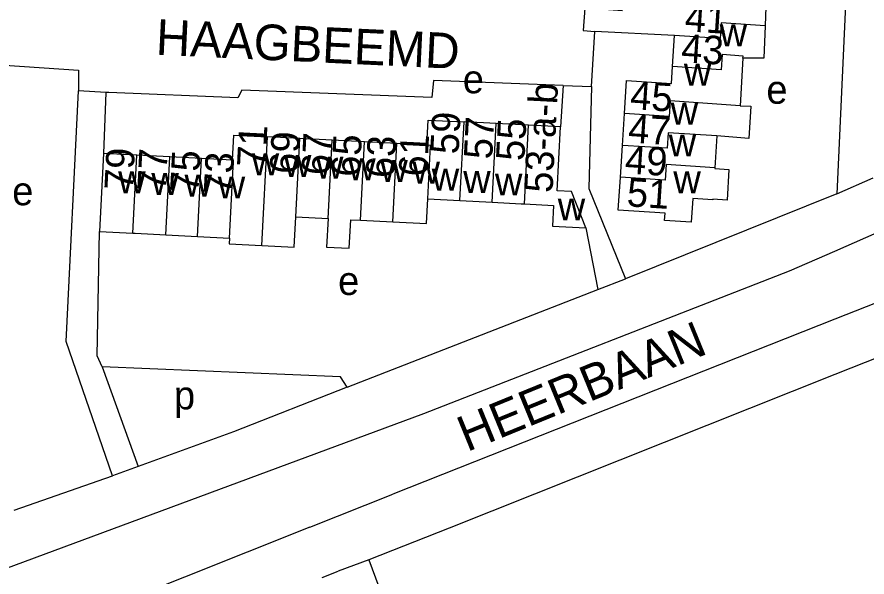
# Model space of a CAD drawing. Extents: x 163026 to 166241, y 382475 to 384501.
# Drawn here: x 164584.9 to 164704.5, y 383524.4 to 383603.1 of the extents above; entities that cross this region are included whole.
import ezdxf

# ---------------------------------------------------------------- set-up
doc = ezdxf.new("R2010")
doc.units = 0
for name, color, linetype in [('BLT_Basislijn', 7, 'Continuous'), ('BLT_Bebouwing', 7, 'Continuous'), ('BLT_Centroide', 7, 'Continuous'), ('BLT_Huisnummer', 7, 'Continuous'), ('BLT_Huisnummer_ tussenligend', 7, 'Continuous'), ('BLT_Huisnummer_reeks', 7, 'Continuous'), ('BLT_Onderverdeling_panden', 7, 'Continuous'), ('BLT_Straatnaam', 7, 'Continuous')]:
    doc.layers.add(name, color=color, linetype=linetype)

msp = doc.modelspace()

# ---------------------------------------------------------------- linework, layer by layer
at = {"layer": 'BLT_Basislijn'}
for p, q in [((164702.47, 383626.32), (164700.28, 383578.28)), ((164597.43, 383592.54), (164593.58, 383592.75)), ((164597.43, 383592.54), (164597.11, 383583.96)), ((164661.76, 383593.51), (164661.4, 383587.68)), ((164661.76, 383593.51), (164665.75, 383593.35)), ((164700.28, 383578.28), (164705.39, 383580.51)), ((164666.65, 383564.81), (164670.52, 383566.32)), ((164631.39, 383551.09), (164666.65, 383564.81)), ((164596.89, 383553.95), (164601.96, 383539.9)), ((164584.51, 383533.77), (164598.35, 383538.59)), ((164626.13, 383531.38), (164637.79, 383536.01)), ((164634.42, 383526.8), (164630.09, 383525.2)), ((164627.88, 383524.32), (164630.09, 383525.2))]:
    msp.add_line(p, q, dxfattribs=at)
for points in [[(164316.74, 383637.52), (164399.59, 383569.15), (164439.68, 383536.44), (164449.09, 383529.98), (164458.65, 383524.65), (164472.19, 383518.92), (164485.74, 383514.54), (164499.92, 383512), (164504.7, 383511.64), (164519.36, 383511.35), (164533, 383512.62), (164547.18, 383515.25), (164581.89, 383525.04), (164642.18, 383547.36), (164693.59, 383567.42), (164700, 383570.19), (164761.7, 383597.42), (164778.75, 383605.71), (164783.1, 383609.13), (164785.13, 383612.46), (164785.97, 383614.66), (164786.37, 383617.55)], [(164665.75, 383593.35), (164666.22, 383601.12)], [(164583.2, 383596.39), (164593.59, 383595.68), (164593.58, 383592.75)], [(164661.76, 383593.51), (164643.54, 383594.21), (164643.27, 383591.84), (164616.57, 383592.86), (164615.99, 383591.79), (164597.85, 383592.51), (164597.43, 383592.54)], [(164598.35, 383538.59), (164591.87, 383557.48), (164593.58, 383592.75)], [(164792.86, 383589.8), (164791.18, 383591.89), (164789.33, 383592.7), (164786.4, 383593.36), (164781.85, 383592.83), (164700, 383560.63), (164637.79, 383536.01)], [(164665.75, 383593.35), (164665.37, 383579.02), (164670.52, 383566.32)], [(164787.8, 383587.61), (164700, 383552.86), (164645.73, 383531.25), (164634.42, 383526.8)], [(164700.28, 383578.28), (164670.52, 383566.32)], [(164664.96, 383573.47), (164666.65, 383564.81)], [(164596.89, 383553.95), (164596.21, 383555.5), (164596.54, 383572.99)], [(164631.39, 383551.09), (164630.44, 383552.51), (164596.89, 383553.95)], [(164631.39, 383551.09), (164615.37, 383544.78), (164601.96, 383539.9)], [(164601.96, 383539.9), (164598.35, 383538.59)], [(164626.13, 383531.38), (164581.76, 383513.72), (164542.95, 383499.41), (164537.38, 383496.5), (164533.86, 383492.72), (164532.63, 383489.75), (164531.89, 383476.11)], [(164634.42, 383526.8), (164642.19, 383505.77), (164655.84, 383454.5)]]:
    msp.add_lwpolyline(points, dxfattribs=at)
at = {"layer": 'BLT_Bebouwing'}
for p, q in [((164690.36, 383606.42), (164690.18, 383601.91)), ((164677.43, 383600.55), (164666.22, 383601.12)), ((164677.15, 383596.16), (164677.43, 383600.55)), ((164670.1, 383585.09), (164670.39, 383589.57)), ((164652.35, 383588.15), (164647.82, 383588.39)), ((164656.88, 383587.92), (164652.35, 383588.15)), ((164661.4, 383587.68), (164656.88, 383587.92)), ((164624.72, 383586.04), (164620.17, 383586.28)), ((164629.26, 383585.81), (164624.72, 383586.04)), ((164633.81, 383585.57), (164629.26, 383585.81)), ((164638.35, 383585.34), (164633.81, 383585.57)), ((164642.58, 383585.12), (164638.35, 383585.34)), ((164683.38, 383586.42), (164683.1, 383581.94)), ((164669.81, 383580.6), (164670.1, 383585.09)), ((164597.11, 383583.96), (164596.54, 383572.99)), ((164601.78, 383583.72), (164597.11, 383583.96)), ((164606.45, 383583.48), (164601.78, 383583.72)), ((164610.9, 383583.24), (164606.45, 383583.48)), ((164615.25, 383583.02), (164610.9, 383583.24)), ((164642.71, 383577.55), (164647.24, 383577.31)), ((164647.24, 383577.31), (164651.77, 383577.08)), ((164624.14, 383575.03), (164628.69, 383574.79)), ((164633.23, 383574.56), (164637.78, 383574.32)), ((164596.54, 383572.99), (164601.21, 383572.75)), ((164605.88, 383572.5), (164610.33, 383572.27)), ((164610.33, 383572.27), (164614.82, 383572.04))]:
    msp.add_line(p, q, dxfattribs=at)
for points in [[(164670.09, 383604.03), (164664.79, 383604.38), (164664.58, 383601.23), (164666.22, 383601.12)], [(164690.18, 383601.91), (164689.99, 383597.36), (164687.05, 383597.33)], [(164687.05, 383597.33), (164687.06, 383597.61), (164684.12, 383597.86), (164683.98, 383595.72)], [(164687.05, 383597.33), (164686.66, 383590.63)], [(164670.39, 383589.57), (164670.69, 383594.2), (164676.99, 383593.79), (164677.15, 383596.16)], [(164686.66, 383590.63), (164688.18, 383590.59), (164687.87, 383586.05), (164683.38, 383586.42)], [(164642.58, 383585.12), (164642.77, 383588.65), (164647.82, 383588.39)], [(164664.96, 383573.47), (164662.94, 383578.59), (164660.94, 383578.71), (164661.4, 383587.68)], [(164615.25, 383583.02), (164615.43, 383586.52), (164620.17, 383586.28)], [(164683.1, 383581.94), (164683.09, 383581.84), (164685.08, 383581.71), (164684.81, 383577.38), (164682.81, 383577.51), (164682.8, 383577.43), (164680.01, 383577.61), (164679.79, 383574.3), (164676.02, 383574.54), (164676.09, 383575.54), (164669.51, 383575.97), (164669.81, 383580.6)], [(164637.78, 383574.32), (164642.54, 383574.08), (164642.71, 383577.55)], [(164651.77, 383577.08), (164655.84, 383576.87), (164656.3, 383576.84)], [(164656.3, 383576.84), (164660.42, 383576.63), (164660.27, 383573.72), (164664.96, 383573.47)], [(164619.38, 383570.99), (164623.92, 383570.76), (164624.14, 383575.03)], [(164628.69, 383574.79), (164628.48, 383570.79), (164631.67, 383570.63), (164631.88, 383574.63), (164633.23, 383574.56)], [(164601.21, 383572.75), (164601.54, 383572.73), (164605.88, 383572.5)], [(164614.82, 383572.04), (164614.78, 383571.23), (164619.38, 383570.99)]]:
    msp.add_lwpolyline(points, dxfattribs=at)
at = {"layer": 'BLT_Onderverdeling_panden'}
for p, q in [((164683.98, 383595.72), (164677.15, 383596.16)), ((164647.24, 383577.31), (164647.82, 383588.39)), ((164651.77, 383577.08), (164652.35, 383588.15)), ((164656.3, 383576.84), (164656.88, 383587.92)), ((164619.38, 383570.99), (164620.17, 383586.28)), ((164624.14, 383575.03), (164624.72, 383586.04)), ((164628.69, 383574.79), (164629.26, 383585.81)), ((164633.23, 383574.56), (164633.81, 383585.57)), ((164637.78, 383574.32), (164638.35, 383585.34)), ((164601.21, 383572.75), (164601.78, 383583.72)), ((164605.88, 383572.5), (164606.45, 383583.48)), ((164610.33, 383572.27), (164610.9, 383583.24))]:
    msp.add_line(p, q, dxfattribs=at)
for points in [[(164690.18, 383601.91), (164683.98, 383602.32), (164683.83, 383600.12), (164677.43, 383600.55)], [(164686.66, 383590.63), (164676.83, 383591.35), (164676.69, 383589.16), (164670.39, 383589.57)], [(164683.38, 383586.42), (164676.54, 383586.87), (164676.39, 383584.68), (164670.1, 383585.09)], [(164642.71, 383577.55), (164643.11, 383585.09), (164642.58, 383585.12)], [(164614.82, 383572.04), (164615.39, 383583.01), (164615.25, 383583.02)], [(164683.1, 383581.94), (164676.24, 383582.39), (164676.1, 383580.19), (164669.81, 383580.6)]]:
    msp.add_lwpolyline(points, dxfattribs=at)

# ---------------------------------------------------------------- texts
at = {"layer": 'BLT_Centroide'}
for s, p in [('w', (164683.77, 383599.03)), ('w', (164678.74, 383593.5)), ('e', (164647.64, 383592.41)), ('e', (164690.35, 383590.94)), ('w', (164676.88, 383588)), ('w', (164676.6, 383583.53)), ('w', (164617.94, 383580.88)), ('w', (164622.47, 383580.64)), ('w', (164626.98, 383580.41)), ('w', (164631.52, 383580.17)), ('w', (164636.03, 383579.94)), ('w', (164640.56, 383579.7)), ('w', (164643.27, 383578.72)), ('w', (164599.16, 383578.34)), ('w', (164603.83, 383578.12)), ('w', (164608.5, 383577.88)), ('w', (164613.17, 383577.62)), ('w', (164647.7, 383578.4)), ('w', (164652.17, 383578.04)), ('w', (164677.26, 383578.34)), ('e', (164584.26, 383576.66)), ('w', (164661, 383574.54)), ('e', (164630.1, 383564.04)), ('p', (164607.01, 383547.95))]:
    msp.add_text(s, height=4, dxfattribs=at).set_placement(p)
at = {"layer": 'BLT_Huisnummer'}
for s, rotation, p in [('43', 356.279, (164678.28, 383596.8)), ('45', 356.279, (164671.1, 383590.21)), ('57', 87.0334, (164651.77, 383583.07)), ('69', 87.0334, (164624.45, 383581)), ('65', 87.0334, (164633.15, 383580.6)), ('61', 87.0334, (164642.6, 383580.64)), ('79', 87.0334, (164601.21, 383578.7)), ('73', 87.0334, (164615.18, 383578.11)), ('51', 356.279, (164670.63, 383576.53))]:
    msp.add_text(s, height=4, rotation=rotation, dxfattribs=at).set_placement(p)
at = {"layer": 'BLT_Huisnummer_ tussenligend'}
for s, rotation, p in [('41', 356.279, (164678.79, 383601.15)), ('59', 87.0334, (164647.04, 383583.77)), ('47', 356.279, (164670.82, 383585.51)), ('71', 87.0334, (164619.86, 383581.94)), ('55', 87.0334, (164656.29, 383582.83)), ('67', 87.0334, (164628.92, 383580.83)), ('63', 87.0334, (164637.97, 383580.43)), ('77', 87.0334, (164605.84, 383578.59)), ('75', 87.0334, (164610.45, 383578.36)), ('49', 356.279, (164670.37, 383581.15))]:
    msp.add_text(s, height=4, rotation=rotation, dxfattribs=at).set_placement(p)
at = {"layer": 'BLT_Huisnummer_reeks'}
msp.add_text('53-a-b', height=4, rotation=87.0334, dxfattribs=at).set_placement((164660.25, 383578.35))
at = {"layer": 'BLT_Straatnaam'}
for s, rotation, p in [('HAAGBEEMD', 357.2832, (164604.4, 383597.85)), ('HEERBAAN', 22.2404, (164648.23, 383541.93))]:
    msp.add_text(s, height=5, rotation=rotation, dxfattribs=at).set_placement(p)

doc.saveas('drawing.dxf')
